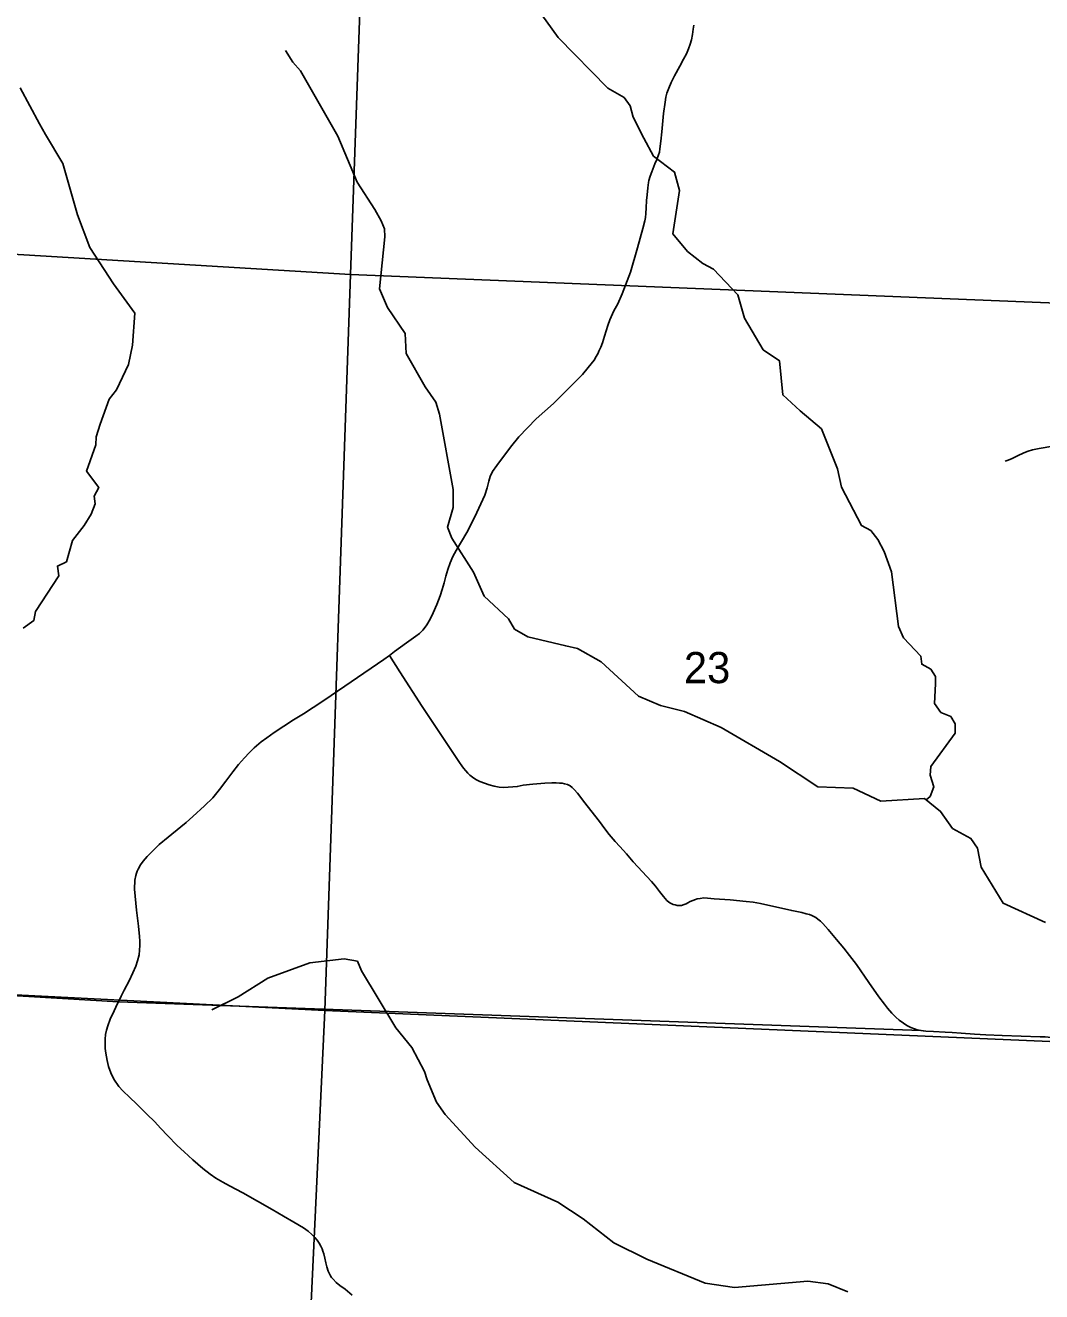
# Model space of a CAD drawing. Extents: x 0 to 34, y 0 to 22.
# Drawn here: x 25.281 to 26.645, y 17.98 to 19.68 of the extents above; entities that cross this region are included whole.
import ezdxf

# ---------------------------------------------------------------- set-up
doc = ezdxf.new("R2010")
doc.units = 0
for name, color, linetype in [('GM_X_Minor_River', 7, 'Continuous'), ('GM_X_Section', 7, 'Continuous'), ('GM_X_Section_Text', 7, 'Continuous'), ('GM_X_Township', 7, 'Continuous'), ('GM_X_Township_Road', 7, 'Continuous')]:
    doc.layers.add(name, color=color, linetype=linetype)

msp = doc.modelspace()

# ---------------------------------------------------------------- linework, layer by layer
at = {"layer": 'GM_X_Minor_River'}
for points in [[(26.4903, 18.64), (26.4959, 18.6446), (26.5004, 18.6575), (26.4958, 18.673), (26.4968, 18.6848), (26.5292, 18.7294), (26.5291, 18.7419), (26.5234, 18.7521), (26.5101, 18.7573), (26.5017, 18.7694), (26.503, 18.796), (26.503, 18.8055), (26.4965, 18.8157), (26.4843, 18.822), (26.4831, 18.833), (26.4599, 18.8575), (26.4533, 18.8727), (26.4438, 18.9462), (26.4338, 18.9735), (26.4254, 18.9897), (26.4159, 19.0014), (26.4037, 19.0082), (26.3765, 19.0596), (26.3715, 19.0842), (26.3499, 19.138), (26.321, 19.1621), (26.2978, 19.1836), (26.2933, 19.2294), (26.2713, 19.2441), (26.2464, 19.2864), (26.2375, 19.3179), (26.2047, 19.3522), (26.1903, 19.3601), (26.1698, 19.3763), (26.1503, 19.4), (26.1594, 19.4578), (26.1525, 19.4827), (26.1243, 19.5042), (26.1113, 19.528), (26.0971, 19.5564), (26.0929, 19.5715), (26.0849, 19.5829), (26.0628, 19.5953), (25.9965, 19.6635), (25.9663, 19.7047)], [(26.6503, 18.4756), (26.5937, 18.5014), (26.5643, 18.5498), (26.5592, 18.5752), (26.5504, 18.5884), (26.5257, 18.6015), (26.5097, 18.6246), (26.488, 18.6419), (26.4296, 18.6385), (26.3924, 18.6558), (26.3447, 18.6574), (26.2933, 18.6916), (26.215, 18.7374), (26.166, 18.7588), (26.1337, 18.7669), (26.1041, 18.7793), (26.0542, 18.8253), (26.0223, 18.8433), (26.0064, 18.8466), (25.9555, 18.8588), (25.9376, 18.8693), (25.9296, 18.883), (25.8969, 18.9135), (25.8827, 18.9456), (25.8536, 18.9914), (25.8478, 19.0061), (25.8553, 19.0327), (25.8555, 19.0566), (25.8368, 19.1578), (25.8321, 19.1737), (25.818, 19.1945), (25.7923, 19.2391), (25.7911, 19.266), (25.7674, 19.3008), (25.7566, 19.3261), (25.7638, 19.3959), (25.7634, 19.4066), (25.7588, 19.4171), (25.7503, 19.4323), (25.7266, 19.4693), (25.7005, 19.531), (25.6504, 19.6187), (25.6401, 19.6304), (25.6302, 19.6459)], [(25.2783, 18.8705), (25.2923, 18.8808), (25.2945, 18.893), (25.326, 18.9409), (25.3241, 18.9538), (25.3362, 18.9596), (25.3443, 18.9884), (25.3601, 19.0083), (25.3695, 19.0235), (25.3748, 19.0375), (25.3736, 19.0478), (25.3796, 19.0592), (25.3632, 19.0811), (25.3755, 19.1168), (25.3762, 19.1274), (25.3814, 19.1442), (25.3937, 19.178), (25.4035, 19.1902), (25.4196, 19.2244), (25.4247, 19.2502), (25.4279, 19.2935), (25.3996, 19.3328), (25.3675, 19.3815), (25.351, 19.4254), (25.3313, 19.4943), (25.308, 19.5329), (25.2999, 19.5473), (25.2743, 19.5957)], [(26.3852, 17.9798), (26.3586, 17.9903), (26.3313, 17.9939), (26.2332, 17.9858), (26.1938, 17.9912), (26.1155, 18.0238), (26.0711, 18.0455), (26.03, 18.0779), (25.9957, 18.1001), (25.9372, 18.1263), (25.8847, 18.1738), (25.8447, 18.2176), (25.8332, 18.2342), (25.8205, 18.2645), (25.817, 18.2754), (25.7998, 18.3076), (25.7784, 18.334), (25.7322, 18.4104), (25.7268, 18.4236), (25.709, 18.4265), (25.6631, 18.4213), (25.6064, 18.4009), (25.5668, 18.3757), (25.5316, 18.3584)]]:
    msp.add_lwpolyline(points, dxfattribs=at)
at = {"layer": 'GM_X_Section'}
for points in [[(24.7666, 20.401), (25.7533, 20.3558), (25.7174, 19.3453), (24.7287, 19.4048)], [(25.7533, 20.3558), (26.7437, 20.3179), (26.7101, 19.3051), (25.7174, 19.3453)], [(24.7287, 19.4048), (25.7174, 19.3453), (25.6829, 18.3575), (24.7007, 18.4069)], [(25.7174, 19.3453), (26.7101, 19.3051), (26.6775, 18.3147), (25.6829, 18.3575)], [(24.7007, 18.4069), (25.6829, 18.3575), (25.6316, 17.2576), (24.6507, 17.2941)], [(26.6775, 18.3147), (26.6394, 17.2767), (26.1369, 17.2827), (26.1357, 17.2414), (25.6316, 17.2576), (25.6829, 18.3575)]]:
    msp.add_lwpolyline(points, close=True, dxfattribs=at)
at = {"layer": 'GM_X_Township'}
for points in [[(24.0167, 18.4402), (24.8943, 18.3993), (25.406, 18.3689), (26.4836, 18.3303), (26.4899, 18.3297), (26.5001, 18.3293), (26.5159, 18.3284), (26.5253, 18.328), (26.5375, 18.3271), (26.5551, 18.3258), (26.5706, 18.3249), (26.5923, 18.324), (26.6434, 18.3221), (26.6499, 18.322)], [(26.6499, 18.322), (26.6434, 18.3221), (26.5923, 18.324), (26.5706, 18.3249), (26.5551, 18.3258), (26.5375, 18.3271), (26.5253, 18.328), (26.5159, 18.3284), (26.5001, 18.3293), (26.4899, 18.3297), (26.4836, 18.3303), (25.406, 18.3689), (24.8943, 18.3993), (24.0167, 18.4402)]]:
    msp.add_lwpolyline(points, dxfattribs=at)
at = {"layer": 'GM_X_Township_Road'}
for points in [[(25.7698, 18.8337), (25.7768, 18.839), (25.7928, 18.8507), (25.8053, 18.8598), (25.8102, 18.8635), (25.8125, 18.8656), (25.8146, 18.8677), (25.8165, 18.87), (25.8199, 18.875), (25.8246, 18.8828), (25.8287, 18.891), (25.8336, 18.9023), (25.838, 18.9138), (25.8408, 18.9225), (25.8432, 18.9314), (25.8454, 18.9404), (25.8481, 18.9493), (25.8513, 18.9581), (25.8551, 18.9666), (25.8595, 18.9749), (25.8737, 18.9989), (25.8795, 19.0099), (25.8872, 19.0256), (25.8978, 19.0491), (25.901, 19.0588), (25.9032, 19.0677), (25.905, 19.0741), (25.9083, 19.0809), (25.9139, 19.089), (25.9323, 19.1135), (25.9436, 19.1275), (25.9668, 19.1513), (25.9899, 19.1721), (26.0119, 19.1938), (26.0291, 19.2111), (26.0367, 19.2206), (26.0407, 19.2252), (26.0446, 19.2303), (26.0474, 19.235), (26.0486, 19.2374), (26.0498, 19.2398), (26.0511, 19.2424), (26.0537, 19.2478), (26.056, 19.2535), (26.0587, 19.2624), (26.0628, 19.2767), (26.0655, 19.2845), (26.0712, 19.2964), (26.0763, 19.3058), (26.0822, 19.3193), (26.0933, 19.3484), (26.1028, 19.3811), (26.1098, 19.4069), (26.1125, 19.4171), (26.1136, 19.4218), (26.1142, 19.4269), (26.1146, 19.4345), (26.1151, 19.4444), (26.1157, 19.4523), (26.1165, 19.4614), (26.1174, 19.4686), (26.1181, 19.4715), (26.1198, 19.4774), (26.1219, 19.4832), (26.1261, 19.4939), (26.1287, 19.4995), (26.1312, 19.5058), (26.1322, 19.5096), (26.1327, 19.514), (26.134, 19.5243), (26.1354, 19.5366), (26.1377, 19.5613), (26.1398, 19.5766), (26.141, 19.5834), (26.1424, 19.5886), (26.1447, 19.5951), (26.148, 19.603), (26.1523, 19.612), (26.1595, 19.6248), (26.1647, 19.6341), (26.1686, 19.6412), (26.1715, 19.6479), (26.1737, 19.6544), (26.1753, 19.66), (26.1765, 19.6672), (26.1775, 19.6744), (26.1783, 19.6797)], [(26.5962, 19.0945), (26.5991, 19.0955), (26.6048, 19.0978), (26.6131, 19.1019), (26.6215, 19.1058), (26.6273, 19.108), (26.6332, 19.1098), (26.6422, 19.1118), (26.6605, 19.1149)], [(25.4049, 18.3667), (25.406, 18.3689), (25.4098, 18.3768), (25.4137, 18.3847), (25.4203, 18.3972), (25.4255, 18.4077), (25.4294, 18.417), (25.4317, 18.4239), (25.4337, 18.4319), (25.4344, 18.4382), (25.4348, 18.4448), (25.4347, 18.4505), (25.4342, 18.4565), (25.4328, 18.4706), (25.4302, 18.4922), (25.4283, 18.5108), (25.4278, 18.5201), (25.4282, 18.5324), (25.4294, 18.5385), (25.4303, 18.5415), (25.4313, 18.5444), (25.4326, 18.5472), (25.4356, 18.5527), (25.4393, 18.5577), (25.4445, 18.564), (25.4519, 18.5714), (25.4609, 18.58), (25.4726, 18.5901), (25.4896, 18.6037), (25.4968, 18.6096), (25.5061, 18.6177), (25.5216, 18.632), (25.5327, 18.6428), (25.5418, 18.6538), (25.5502, 18.6652), (25.5595, 18.6777), (25.5671, 18.6874), (25.5753, 18.6966), (25.5817, 18.7033), (25.5884, 18.7098), (25.5977, 18.7178), (25.6051, 18.7235), (25.6152, 18.7306), (25.6281, 18.7392), (25.6412, 18.7474), (25.6544, 18.7555), (25.6675, 18.7639), (25.6829, 18.7744), (25.7625, 18.8284), (25.7698, 18.8337)], [(26.4862, 18.3301), (26.4836, 18.3303), (26.4784, 18.3314), (26.4748, 18.3326), (26.4698, 18.3347), (26.4644, 18.3374), (26.4598, 18.3405), (26.454, 18.3446), (26.4494, 18.3486), (26.4441, 18.354), (26.4383, 18.3604), (26.4342, 18.3658), (26.427, 18.3759), (26.4133, 18.3951), (26.3969, 18.4189), (26.3875, 18.4313), (26.3797, 18.441), (26.3698, 18.4528), (26.3586, 18.4663), (26.3516, 18.474), (26.3483, 18.4774), (26.3451, 18.4799), (26.3421, 18.482), (26.3394, 18.4837), (26.3367, 18.4849), (26.3335, 18.4861), (26.3293, 18.4873), (26.3232, 18.4888), (26.3098, 18.4915), (26.2679, 18.5011), (26.2582, 18.5027), (26.2488, 18.5038), (26.2272, 18.5057), (26.2059, 18.5073), (26.1967, 18.5081), (26.1917, 18.5084), (26.187, 18.5078), (26.1829, 18.5072), (26.1806, 18.5065), (26.1769, 18.5052), (26.1736, 18.5036), (26.1703, 18.5018), (26.168, 18.5006), (26.1653, 18.4995), (26.1619, 18.4985), (26.1588, 18.4982), (26.156, 18.4984), (26.1532, 18.499), (26.1506, 18.4997), (26.1472, 18.5015), (26.1449, 18.5029), (26.1422, 18.5051), (26.1376, 18.5105), (26.1325, 18.5171), (26.127, 18.5241), (26.1217, 18.5303), (26.0972, 18.5568), (26.088, 18.5676), (26.0792, 18.5776), (26.0729, 18.5844), (26.0648, 18.5938), (26.0591, 18.6011), (26.0518, 18.6111), (26.0402, 18.6258), (26.0322, 18.6363), (26.0222, 18.649), (26.0179, 18.6539), (26.0151, 18.6567), (26.0123, 18.6587), (26.0088, 18.6605), (26.005, 18.6617), (26.0017, 18.6625), (25.998, 18.6627), (25.9936, 18.6631), (25.988, 18.663), (25.9784, 18.6623), (25.9625, 18.6612), (25.9493, 18.6597), (25.9413, 18.658), (25.9353, 18.6576), (25.9291, 18.657), (25.9233, 18.6567), (25.9172, 18.6573), (25.9104, 18.6584), (25.9039, 18.6603), (25.8976, 18.6624), (25.8913, 18.6647), (25.8858, 18.6675), (25.8814, 18.6704), (25.8779, 18.6732), (25.8752, 18.6758), (25.8723, 18.6789), (25.8693, 18.6825), (25.867, 18.6856), (25.8638, 18.6904), (25.853, 18.7065), (25.8431, 18.7213), (25.8138, 18.7654), (25.7838, 18.812), (25.7698, 18.8337)], [(25.7197, 17.9754), (25.7105, 17.9832), (25.7031, 17.9884), (25.6984, 17.9924), (25.6941, 17.9968), (25.6922, 17.9992), (25.6908, 18.0011), (25.6893, 18.004), (25.6877, 18.0076), (25.6857, 18.0131), (25.6844, 18.0186), (25.683, 18.025), (25.6817, 18.0306), (25.6806, 18.0342), (25.6793, 18.0377), (25.6779, 18.041), (25.6756, 18.045), (25.673, 18.0489), (25.6698, 18.0526), (25.6657, 18.0567), (25.6609, 18.061), (25.6544, 18.0658), (25.6417, 18.0734), (25.6274, 18.0815), (25.6123, 18.0904), (25.5729, 18.1128), (25.5549, 18.1222), (25.5462, 18.1268), (25.5369, 18.1322), (25.5293, 18.1375), (25.5195, 18.1451), (25.5061, 18.157), (25.4941, 18.1677), (25.485, 18.1762), (25.4721, 18.1894), (25.4629, 18.1991), (25.4543, 18.2082), (25.4448, 18.2177), (25.4376, 18.2248), (25.4303, 18.232), (25.4214, 18.2404), (25.4119, 18.2495), (25.4065, 18.2552), (25.3998, 18.2651), (25.3958, 18.2735), (25.3928, 18.2821), (25.3909, 18.2902), (25.3889, 18.3002), (25.3882, 18.3064), (25.388, 18.3126), (25.3881, 18.3188), (25.3888, 18.325), (25.39, 18.331), (25.3917, 18.337), (25.395, 18.3457), (25.4001, 18.357), (25.4049, 18.3667)], [(26.6653, 18.3191), (26.6635, 18.3199), (26.6605, 18.3207), (26.6574, 18.3212), (26.6542, 18.3216), (26.6499, 18.322), (26.6434, 18.3221), (26.5923, 18.324), (26.5706, 18.3249), (26.5551, 18.3258), (26.5375, 18.3271), (26.5253, 18.328), (26.5159, 18.3284), (26.5001, 18.3293), (26.4899, 18.3297), (26.4862, 18.3301)]]:
    msp.add_lwpolyline(points, dxfattribs=at)

# ---------------------------------------------------------------- texts
at = {"layer": 'GM_X_Section_Text'}
msp.add_text('23', height=0.04186, rotation=0, dxfattribs=at).set_placement((26.1651, 18.7967))

doc.saveas('drawing.dxf')
